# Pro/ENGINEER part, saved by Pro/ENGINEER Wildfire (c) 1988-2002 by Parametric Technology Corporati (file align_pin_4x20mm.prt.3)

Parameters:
  PTNUM = "A_1B_3-Y48048"
  PTNAME = "20_DEG_PRESSURE_ANGLE_BEVEL_GEARS-48,32_&_24_PITCH"
  MFG = "Stock_Drive_Products"
  WEIGHT = "*"
  MATERIAL = "BRASS"
  DIAMETRICAL_PITCH = "48"
  TEETH = "48"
